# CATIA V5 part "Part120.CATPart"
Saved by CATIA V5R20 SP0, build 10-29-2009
Part number: IA 4717SF
Revision: ANY
Definition: UNKNOWN
Nomenclature: IA 4717SF
Source: Unknown
Bounding box of the stored display mesh (mm): x -2.35 to 2.35, y -7.925 to 9.045, z -2.35 to 2.35
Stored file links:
  C:\Users\Utente\Desktop\IO LAVORO\3D X SITO CF\CUMSA\3D files FA\FA 084700\Part120.CATPart

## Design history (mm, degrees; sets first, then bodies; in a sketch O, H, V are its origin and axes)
Body1 "Cortar-Extruir2" (main body)
  Solid1: solid without history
